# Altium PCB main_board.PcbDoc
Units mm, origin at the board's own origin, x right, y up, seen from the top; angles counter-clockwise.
Board outline 36 x 36 mm, 2 copper layers (Top Layer, Bottom Layer); 78 components, 59 nets, 251 pads, 295 vias.
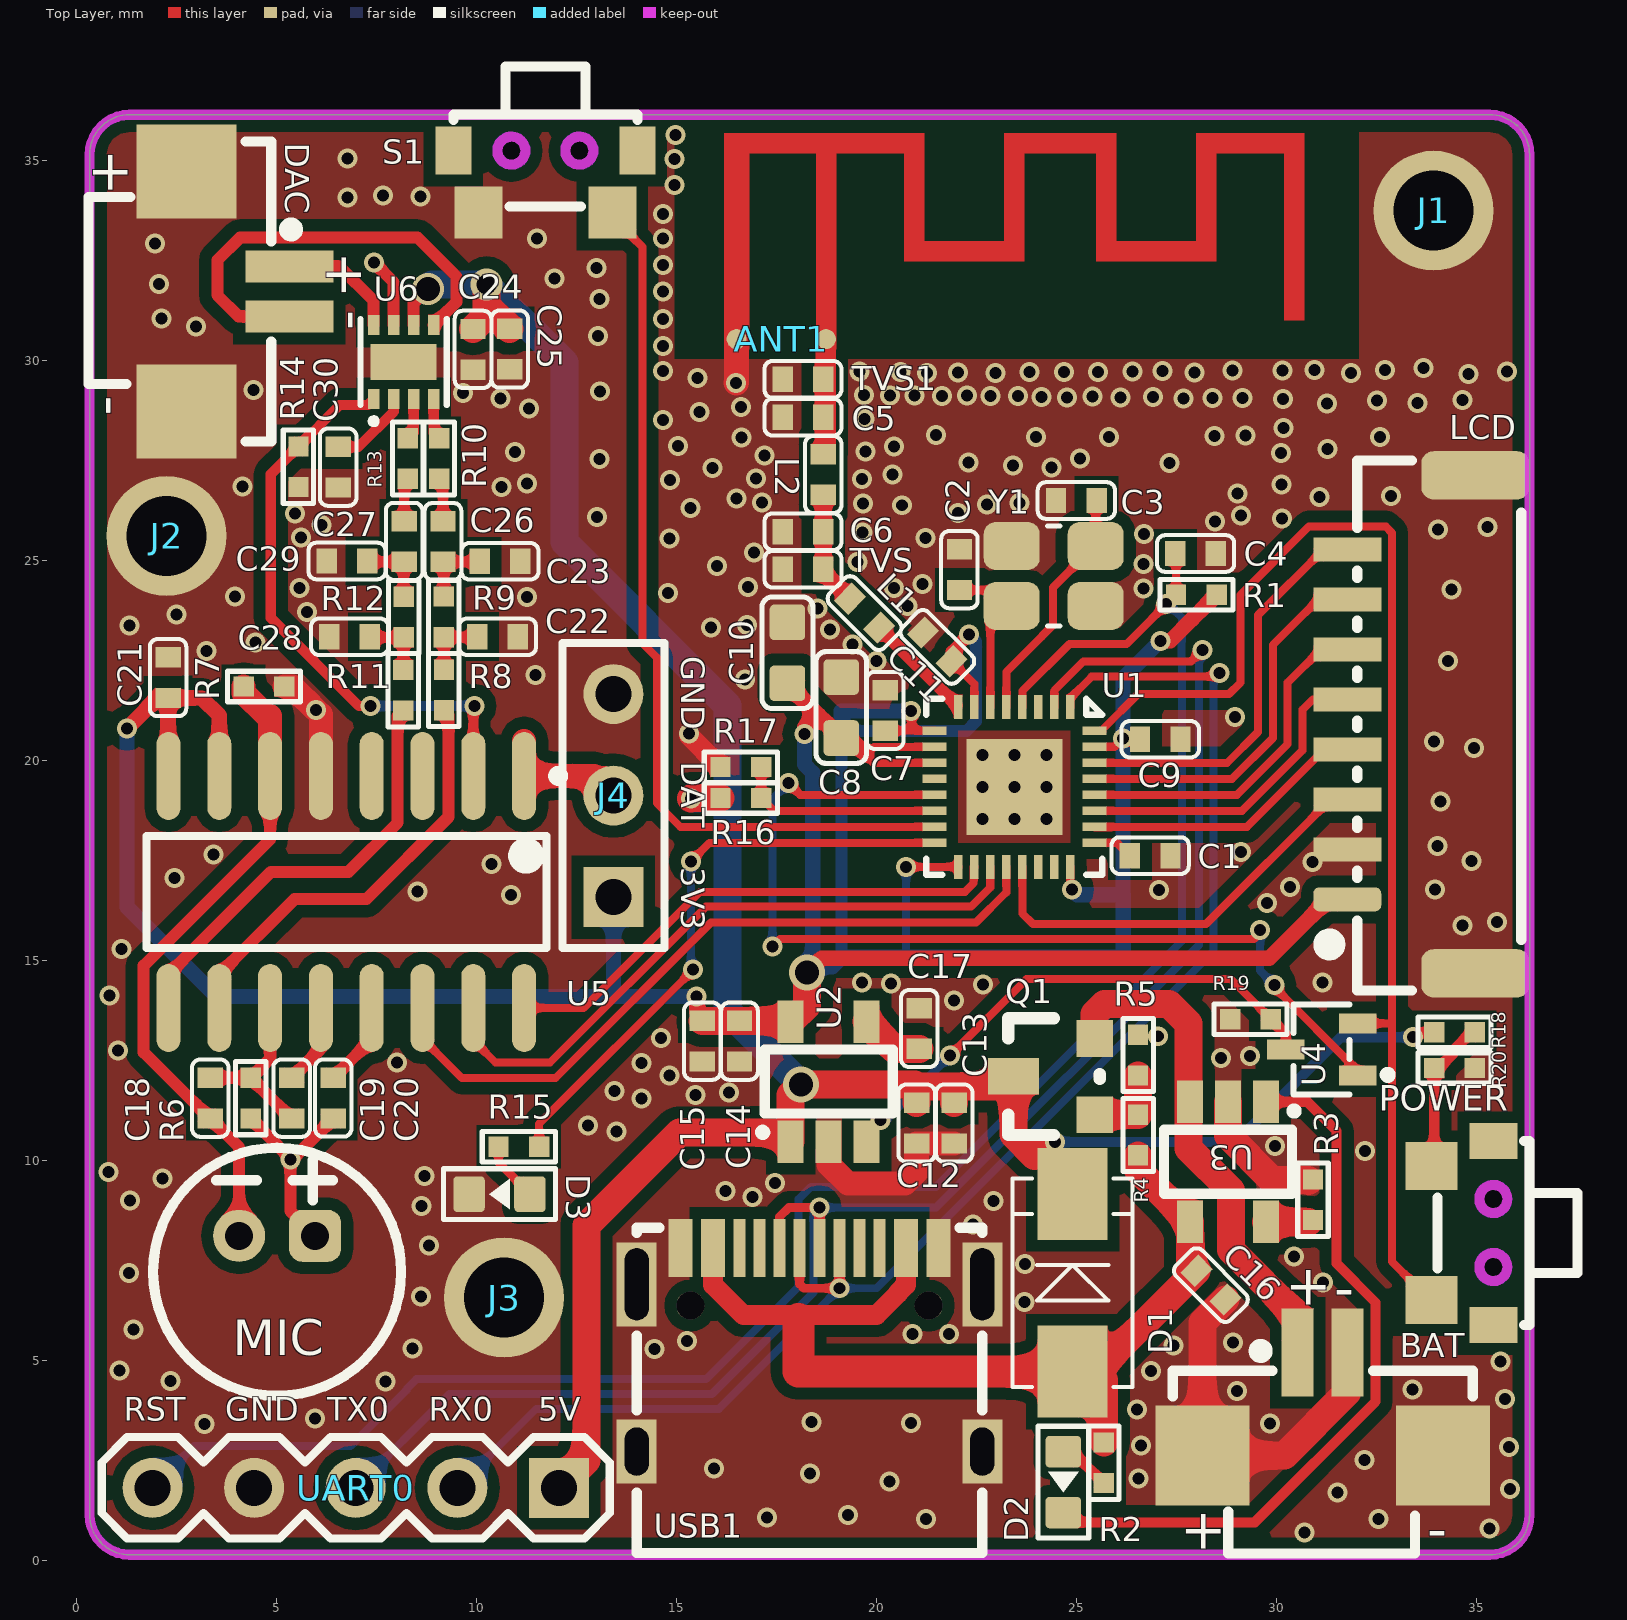
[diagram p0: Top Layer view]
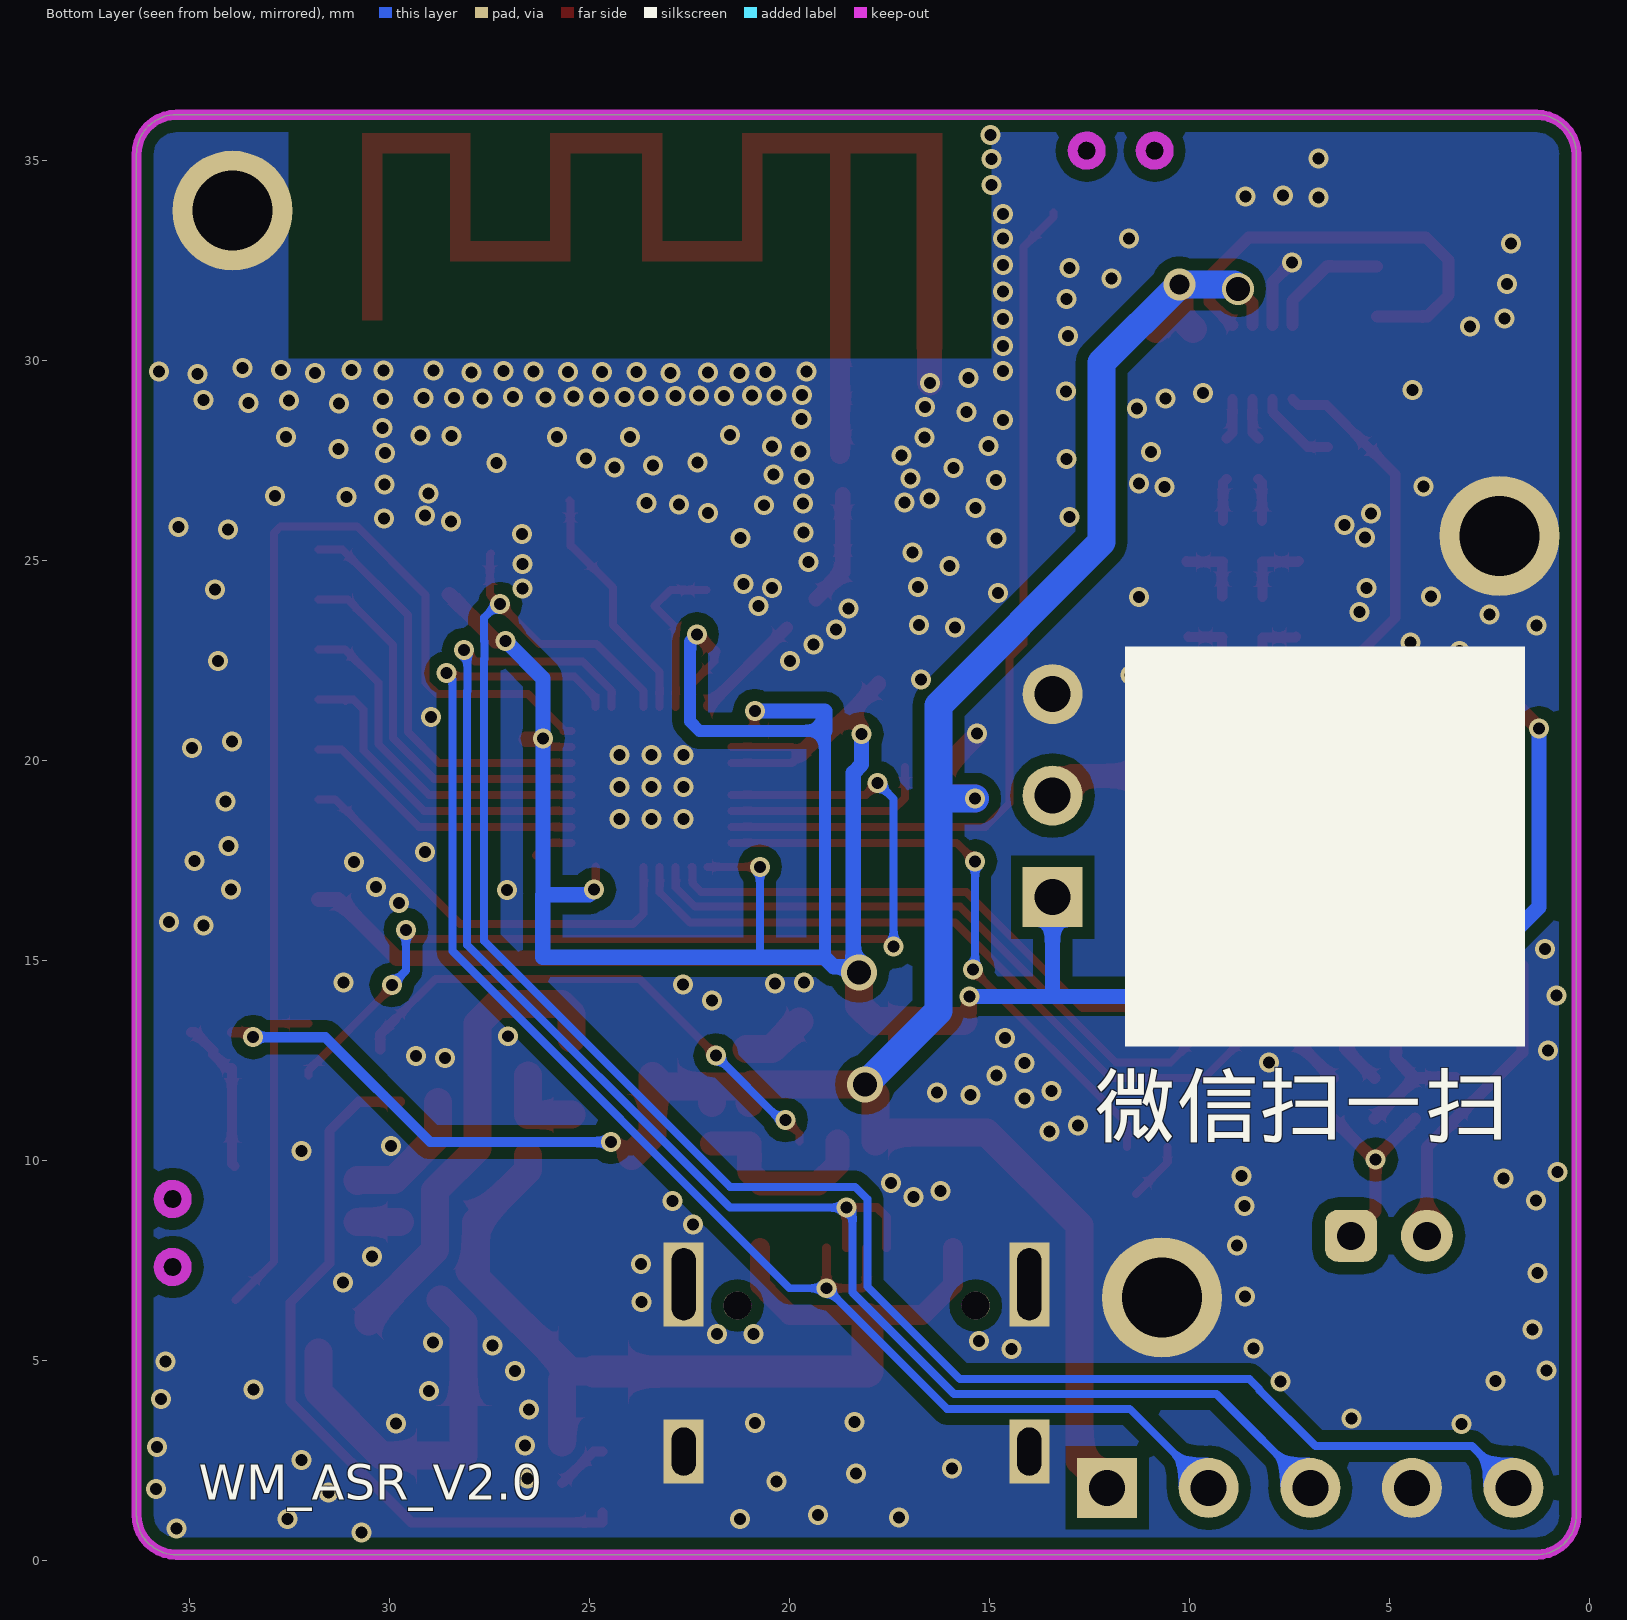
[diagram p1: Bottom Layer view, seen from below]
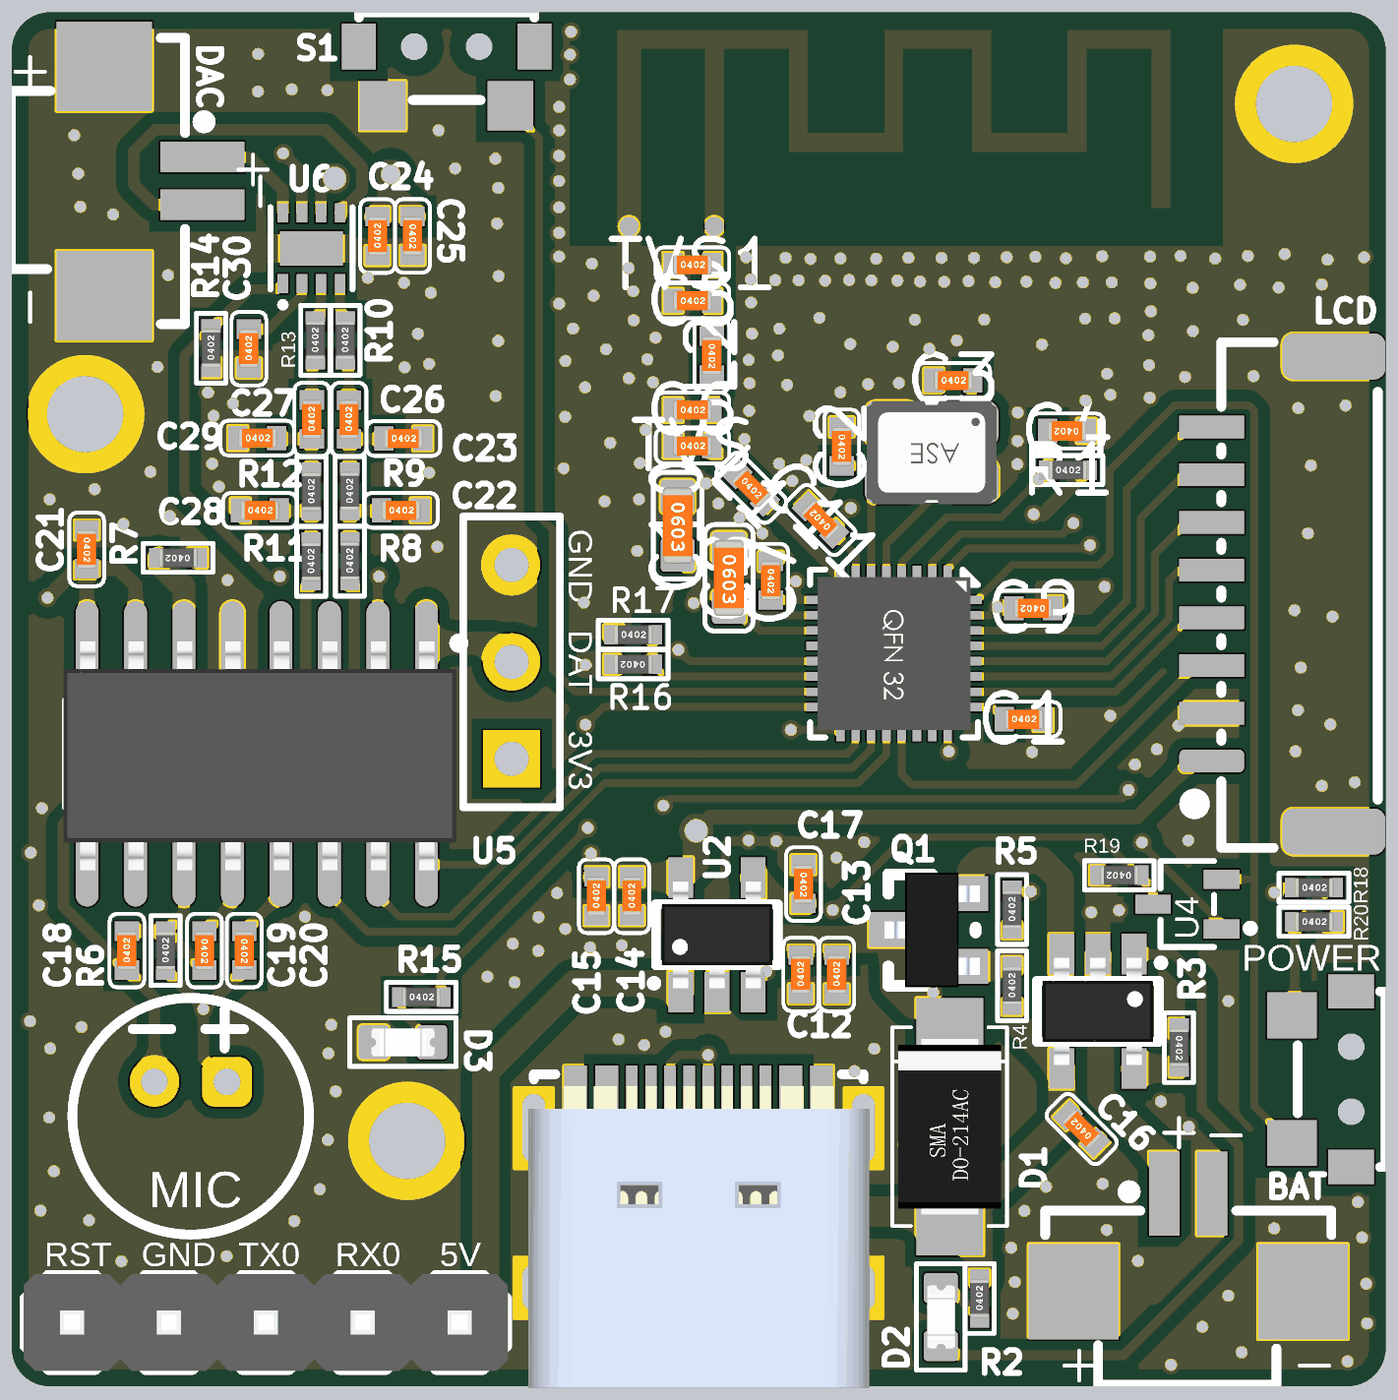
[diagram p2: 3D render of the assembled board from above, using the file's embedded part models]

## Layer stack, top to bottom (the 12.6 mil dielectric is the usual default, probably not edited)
Top Solder: solder mask 0.0102, Solder Resist, Dk 3.5
Top Layer: signal copper 0.0356
Dielectric 1: dielectric 0.32, FR-4, Dk 4.8
Bottom Layer: signal copper 0.0356
Bottom Solder: solder mask 0.0102, Solder Resist, Dk 3.5

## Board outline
0.338,1.149 ccw(c1.338,1.149) 1.338,0.149 35.338,0.149 ccw(c35.338,1.149) 36.338,1.149 36.338,35.149 ccw(c35.338,35.149) 35.338,36.149 1.338,36.149 ccw(c1.338,35.149) 0.338,35.149

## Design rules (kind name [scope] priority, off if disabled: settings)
Clearance Clearance_freep_ad [HasPad('Free-6') Or HasPad('Free-7') Or HasPad('Free-8') or HasPad('Free-HOLE')] p1: gap=1
Clearance polygon [inpolygon] p2: gap=0.3
Clearance ic [HasFootprint('LQFP48_N') Or HasFootprint('HMC5883L')or HasFootprint('RP4')or HasFootprint('USBMICRO2') Or HasFootprint('JP2_SMD')] p3: gap=0.102
Clearance [All And Not IsKeepOut vs All And Not IsKeepOut] p4: gap=0.17
ComponentClearance [InComponent('J1') vs InComponent('SW1')] p1 off: gap=0 collisioncheckmode=3 verticalgap=2540 showdistances=FALSE
DiffPairsRouting [All] p1: maxlimit=0.254 minlimit=0.2 mostfreqgap=0.2 toplayer_minwidth=0.381 toplayer_maxwidth=0.381 toplayer_prefwidth=0.381 bottomlayer_minwidth=0.381 bottomlayer_maxwidth=0.381 bottomlayer_prefwidth=0.381 maxuncoupledlength=12.7
FabricationTestpoint [(IsPad And (OnTopLayer Or OnBottomLayer))] p1: side=3 testpointundercomponent=TRUE minsize=1.016 maxsize=2.54 preferedsize=1.524 minholesize=0 maxholesize=1.016 preferedholesize=0.813 testpointgrid=0.025 allowsidetop=TRUE allowsidebottom=TRUE usegrid=TRUE gridtolerance=0
HoleSize [All] p1: absolutevalues=TRUE maxlimit=5.08 minlimit=0.152 maxpercent=80.000 minpercent=20.000
MinimumSolderMaskSliver [All] p1: minsoldermaskwidth=0.025
PolygonConnect PolygonConnect_1 [isvia] p1: connectstyle=Direct reliefconductorwidth=0.254 reliefentries=4 polygonreliefangle="90 Angle" airgapwidth=0.254
PolygonConnect [All] p2: connectstyle=Direct reliefconductorwidth=0.254 reliefentries=4 polygonreliefangle="90 Angle" airgapwidth=0.254
RoutingVias [All] p1: holewidth=0.35 width=0.7 viastyle="Through Hole" minholewidth=0.3 minwidth=0.35 maxholewidth=10 maxwidth=10
ShortCircuit [InNet('ANT1') vs InNet('GND')] p1: allowed=TRUE
SilkToSilkClearance [All] p1: silktosilkclearance=0
SilkToSolderMaskClearance SilkscreenOverComponentPads [IsPad] p1 off: minsilkscreentomaskgap=0.051 clearancetoexposedcopper=TRUE
SolderMaskExpansion [All] p1: expansion=0.051
Width Width_1 [InNet('VCC')] p1: maxlimit=25.4 minlimit=0.178 preferedwidth=0.635
Width [All] p2: maxlimit=10 minlimit=0.2 preferedwidth=0.254
22 further rules are at their usual default settings.

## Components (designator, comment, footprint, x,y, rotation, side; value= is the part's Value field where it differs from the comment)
ANT1 "PCB_ANT" MINI_ANT 18.747,30.517 r270 top
BAT "Header 2" CONN-SMD_2P-P1.25-HC-1.25-2PWT 31.165,3.914 r0 top locked
C1 "4.7uF/6.3V" C0402#1 26.853,17.628 r0 top
C2 "15pF" C0402#1 22.084,24.775 r270 top
C3 "15pF" C0402#1 25.006,26.505 r0 top
C4 "1uF/6.3V" C0402#1 27.987,25.18 r180 top
C5 "1pF" C0402#1 18.172,28.589 r0 top
C6 "1pF" C0402#1 18.172,25.725 r0 top
C7 "1nF/16V" C0402#1 20.226,21.257 r270 top
C8 "C0603/47uF/6.3V" C0603 19.129,21.329 r270 top locked
C9 "1uF/6.3V" C0402#1 27.104,20.536 r180 top
C10 "C0603/10uF/6.3V" C0603 17.784,22.697 r270 top
C11 "1uF/6.3V" C0402#1 21.53,22.845 r135 top
C12 "10uF" C0402#1 21.013,10.94 r90 top
C13 "100nF" C0402#1 21.953,10.94 r90 top
C14 "100nF" C0402#1 16.585,12.988 r90 top
C15 "10uF" C0402#1 15.655,12.988 r90 top
C16 "10uF" C0402#1 28.372,6.888 r135 top
C17 "22nF" C0402#1 21.08,13.305 r270 top
C18 "4.7uF/6.3V" C0402#1 3.355,11.563 r90 top
C19 "1uF/6.3V" C0402#2 3.349,11.563 r270 top
C20 "1uF/6.3V" C0402#1 6.428,11.564 r270 top
C21 "4.7uF/6.3V" C0402#1 2.299,22.077 r270 top
C22 "100pF" C0402#1 10.536,23.1 r0 top
C23 "100pF" C0402#1 10.597,24.984 r0 top
C24 "1uF/6.3V" C0402#1 9.922,30.285 r90 top
C25 "10uF/6.3V" C0402#1 10.839,30.29 r270 top
C26 "220nF" C0402#1 9.172,25.481 r90 top
C27 "220nF" C0402#1 8.201,25.482 r90 top
C28 "100pF" C0402#3 4.165,22.593 r0 top
C29 "100pF" C0402#1 6.772,24.993 r0 top
C30 "1uF/6.3V" C0402#4 5.756,27.494 r90 top
D1 "SS14" DO-214 24.915,6.948 r90 top locked
D2 "D0603_Red" D0603 24.682,1.964 r270 top locked
D3 "D0603_Blue" D0603 10.585,9.164 r180 top
DAC "Header 2" CONN-SMD_2P-P1.25-HC-1.25-2PWT 4.044,31.73 r270 top locked
J1 "M3" "M3 125X200" 33.938,33.749 r0 top
J2 "M3" "M3 125X200" 2.261,25.619 r0 top
J3 "M3" "M3 125X200" 10.7,6.578 r0 top
J4 "Header 3" HDR1X3 13.435,16.587 r90 top
L1 "8.2pF" 0402C 19.711,23.689 r315 top
L2 "2.4nH" 0402C 18.68,27.154 r270 top
LCD "Header_10" CONN-SMD_SM08B-GHS-TB-LF-SN 33.38,20.907 r90 top locked
MIC "GMI6027P-2C30DB" MIC-TH_BD6.0-P1.90-D0.4-L 5.026,7.223 r180 top
POWER "TS24CA" SW-SMD_TS24CA 35.432,10.492 r270 top (schematic designator Power)
Q1 "PMOS/AO3401" SOT-23 24.449,12.102 r90 top
R1 "4.7K" R0402 28.007,24.152 r0 top locked
R2 "1K" R0402 25.695,2.448 r90 top
R3 "1.65K" R0402 30.923,9.023 r270 top
R4 "10K" R0402 26.549,10.64 r90 top
R5 "100K" R0402 26.549,12.639 r90 top
R6 "2.2K" R0402 4.369,11.563 r90 top
R7 "0R" R0402 4.697,21.855 r180 top
R8 "40.2K" R0402 9.196,21.769 r90 top
R9 "40.2K" R0402 9.193,23.597 r90 top
R10 "22K" R0402 9.078,27.553 r90 top
R11 "40.2K" R0402 8.182,21.761 r90 top
R12 "40.2K" R0402 8.188,23.591 r90 top
R13 "22K" R0402 8.291,27.553 r90 top
R14 "100K" R0402 5.559,27.348 r90 top
R15 "1K" R0402 11.068,10.347 r0 top
R16 "10K/±1%" R0402 16.619,19.067 r180 top
R17 "10K/±1%" R0402 16.619,19.841 r0 top
R18 "5.1K" R0402 34.46,13.213 r0 top
R19 "1M" R0402 29.358,13.539 r180 top
R20 "10K" R0402 34.46,12.318 r0 top
S1 "TS24CA" SW-SMD_TS24CA 9.432,35.251 r0 top
TVS "BUE03CN10" C0402#1 18.172,24.787 r0 top
TVS1 "BUE03CN10" C0402#1 18.172,29.533 r0 top
U1 "W800" QFN32_4X4 23.455,19.348 r270 top locked
U2 "DS8572" SOT-23-5 18.815,11.978 r90 top locked
U3 "LTC4054" SOT-23-5 28.798,9.972 r270 top
U4 "BAT54CW" SOT-323-3_L2.0-W1.3-P1.30-LS2.3-BR 31.139,12.781 r0 top
U5 "WM8211" SOP-16 6.756,16.719 r270 top locked
U6 "HAA9209" DFN-8_L2.0-W2.0-P0.50-BL-EP 8.19,29.966 r0 top
UART0 "Header_5" PH_5PIN_DIP_2.54MM_180DEG 12.071,1.823 r180 top locked
USB1 "Type-C 母座 卧贴-直插" "Type-C 母座 卧贴-直插" 22.655,6.908 r0 top locked
Y1 "40MHz" OSC-TZ1067B 24.441,24.615 r180 top

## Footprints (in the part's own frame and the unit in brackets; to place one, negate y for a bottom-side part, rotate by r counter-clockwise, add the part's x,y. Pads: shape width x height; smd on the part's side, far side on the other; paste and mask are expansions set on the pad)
0402C [mil]
  rect 20x25 smd: 1(-20,0) 2(20,0)
  silkscreen extent -38,-18 38,18, body extent -20,-10 20,10, height 20
C0402#1 [mil]
  rect 20x25 smd: 1(-20,0) 2(20,0)
  silkscreen extent -38,-18 38,18, body extent -20,-10 20,10, height 20
C0402#2 [mil]
  rect 20x25 smd: 1(-20,80.28) 2(20,80.28)
  silkscreen extent -38,62 38,98, body extent -20,70 20,90, height 20
C0402#3 [mil]
  rect 20x25 smd: 1(85.2,19.92) 2(125.2,19.92)
  silkscreen extent 67,2 143,38, body extent 85,10 125,30, height 20
C0402#4 [mil]
  rect 20x25 smd: 1(-26.14,-31.3) 2(13.86,-31.3)
  silkscreen extent -44,-49 32,-13, body extent -26,-41 14,-21, height 20
C0603 [mil]
  rrect25% 35x35 smd: 1(-30,0) 2(30,0)
  silkscreen extent -55,-25 55,25, body extent -39,-15 39,16, height 31
CONN-SMD_2P-P1.25-HC-1.25-2PWT [mm]
  rect 0.8x2.2 smd paste+0 mask+0.05: 1(-0.625,1.285) 2(0.625,1.285)
  rect 2.35x2.5 smd paste+0 mask+0.05: 3(-3.005,-1.285) 4(3.005,-1.285)
  silkscreen extent -3.75,-3.73 3.75,1.48
CONN-SMD_SM08B-GHS-TB-LF-SN [mm]
  rrect50% 0.6x1.7 smd paste+0 mask+0.05: 1(-4.375,1.6)
  rect 0.6x1.7 smd paste+0 mask+0.05: 2(-3.125,1.6) 3(-1.875,1.6) 4(-0.625,1.6) 5(0.625,1.6) 6(1.875,1.6) 7(3.125,1.6) 8(4.375,1.6)
  rrect50% 1.21x2.7 smd paste+0 mask+0.05: 9(-6.225,-1.6) 10(6.225,-1.6)
  silkscreen extent -6.65,-2.75 6.6,2.25
D0603 [mil]
  rrect25% 31x35 smd: 1(-30,0) 2(30,0)
  silkscreen extent -55,-25 55,25, body extent -32,-14 32,15, height 27
DFN-8_L2.0-W2.0-P0.50-BL-EP [mm]
  rect 0.28x0.505 smd: 1(-0.75,-0.928) 2(-0.25,-0.928) 3(0.25,-0.928) 4(0.75,-0.928) 5(0.75,0.928) 6(0.25,0.928) 7(-0.25,0.928) 8(-0.75,0.928)
  rect 1.65x0.9 smd: 9(0,0)
  silkscreen extent -1.08,-1.55 1.08,1.08
DO-214 [mm]
  rect 2.3x1.75 smd: 1(-2.222,0) 2(2.223,0)
  silkscreen extent -2.6,-1.5 2.6,1.5, body extent -2.3,-1.35 2.3,1.35, height 2.4
HDR1X3 [mm] "Connector; Header; 3 Position"
  rect 1.5x1.5 hole 0.9: 1(0,0)
  round 1.5 hole 0.9: 2(2.54,0) 3(5.08,0)
  silkscreen extent -1.27,-1.27 6.35,1.27
"M3 125X200" [mm] "M3螺丝孔，孔125Mil，焊盘200Mil"
  round 3 hole 2: 1(0,0)
MIC-TH_BD6.0-P1.90-D0.4-L [mm]
  rrect50% 1.3x1.3 hole 0.7: 1(-0.95,-0.9)
  round 1.3 hole 0.7: 2(0.95,-0.9)
  silkscreen extent -3.1,-3.1 3.1,3.1
MINI_ANT [mm]
  rrect100% 0.5x0.5 smd: 1(-0.023,0) 2(-0.023,-2.236)
  Top Layer region: -4.673,-2.549 -5.173,-2.549 -5.173,2.451 -2.473,2.451 -2.473,4.451 -5.173,4.451 -5.173,7.251 -2.473,7.251 -2.473,9.251 -5.173,9.251 -5.173,11.951 -0.5,11.951 -0.5,11.451 -4.673,11.451 -4.673,9.751 -1.973,9.751 -1.973,6.751 -4.673,6.751 -4.673,4.951 -1.973,4.951 -1.973,1.951 -4.673,1.951 -4.673,0.251 0.227,0.251 0.227,-0.249 -4.673,-0.249 -4.673,-2.549
  Top Layer region: -4.926,-2.549 0.227,-2.549 0.227,-1.922 -4.926,-1.922 -4.926,-2.549
OSC-TZ1067B [mm]
  rrect50% 1.4x1.2 smd: 1(-1.05,-0.75) 2(1.05,-0.75) 3(1.05,0.75) 4(-1.05,0.75)
  silkscreen extent -0.15,-1.25 0.15,1.25, body extent -1.7,-1.35 1.7,1.35, height 1.06
PH_5PIN_DIP_2.54MM_180DEG [mm]
  rect 1.5x1.5 hole 0.9: 1(0,0)
  round 1.5 hole 0.9: 2(2.54,0) 3(5.08,0) 4(7.62,0) 5(10.16,0)
  silkscreen extent -1.27,-1.27 11.43,1.27, body extent -1.27,-1.27 11.43,1.27, height 8.02
QFN32_4X4 [mm]
  rect 0.6x0.22 smd: 1(-2,1.4) 2(-2,1) 3(-2,0.6) 4(-2,0.2) 5(-2,-0.2) 6(-2,-0.6) 7(-2,-1) 8(-2,-1.4) 17(2,-1.4) 18(2,-1) 19(2,-0.6) 20(2,-0.2) 21(2,0.2) 22(2,0.6) 23(2,1) 24(2,1.4)
  rect 0.22x0.6 smd: 9(-1.4,-2) 10(-1,-2) 11(-0.6,-2) 12(-0.2,-2) 13(0.2,-2) 14(0.6,-2) 15(1,-2) 16(1.4,-2) 25(1.4,2) 26(1,2) 27(0.6,2) 28(0.2,2) 29(-0.2,2) 30(-0.6,2) 31(-1,2) 32(-1.4,2)
  rect 2.4x2.4 smd: 33(0,0)
  silkscreen extent -2.2,-2.2 2.2,2.2, body extent -2,-2 2,2, height 0.57
R0402 [mil]
  rect 20x20 smd: 1(-20,0) 2(20,0)
  silkscreen extent -36,-15 36,15, body extent -20,-10 20,10, height 20
SOP-16 [mm]
  oval 2.2x0.6 smd: 1(-2.9,4.445) 2(-2.9,3.175) 3(-2.9,1.905) 4(-2.9,0.635) 5(-2.9,-0.635) 6(-2.9,-1.905) 7(-2.9,-3.175) 8(-2.9,-4.445) 9(2.9,-4.445) 10(2.9,-3.175) 11(2.9,-1.905) 12(2.9,-0.635) 13(2.9,0.635) 14(2.9,1.905) 15(2.9,3.175) 16(2.9,4.445)
  silkscreen extent -3.02,-5 1.4,5.42, body extent -2.95,-5.07 3.05,5.23, height 2.11
SOT-23 [mil]
  rect 36x36 smd: 1(-37.5,-40) 2(37.5,-40)
  rect 36x50 smd: 3(0.5,40)
  silkscreen extent -58,-45 58,45, body extent -59,-49 59,49, height 41
SOT-23-5 [mm]
  rect 1.06x0.65 smd: 1(-1.5,0.95) 2(-1.5,0) 3(-1.5,-0.95) 4(1.5,-0.95) 5(1.5,0.95)
  silkscreen extent -1.33,-1.6 0.8,1.71, body extent -1.4,-1.45 1.4,1.45, height 1.45
SOT-323-3_L2.0-W1.3-P1.30-LS2.3-BR [mm]
  rect 0.936x0.5 smd: 1(0.898,-0.65) 2(0.898,0.65) 3(-0.898,0)
  silkscreen extent -0.7,-1.13 1.75,1.13
SW-SMD_TS24CA [mm]
  rect 0.9x1.2 smd: 1(0,0) 2(4.6,0)
  rect 1.2x1.3 smd: 3(0.625,-1.55) 4(3.975,-1.55)
  Keep-Out Layer circle w0.005: c3.15,0 r0.35
  Keep-Out Layer circle w0.005: c1.45,0 r0.35
  Keep-Out Layer board cut-out: 1.45,0.35 1.38,0.35 1.252,0.297 1.153,0.198 1.1,0.07 1.1,-0.07 1.153,-0.198 1.252,-0.297 1.38,-0.35 1.45,-0.35 1.52,-0.35 1.648,-0.297 1.747,-0.198 1.8,-0.07 1.8,0.07 1.747,0.198 1.648,0.297 1.52,0.35 1.45,0.35 1.45,0.35
  Keep-Out Layer board cut-out: 3.15,0.35 3.08,0.35 2.952,0.297 2.853,0.198 2.8,0.07 2.8,-0.07 2.853,-0.198 2.952,-0.297 3.08,-0.35 3.15,-0.35 3.22,-0.35 3.348,-0.297 3.447,-0.198 3.5,-0.07 3.5,0.07 3.447,0.198 3.348,0.297 3.22,0.35 3.15,0.35 3.15,0.35
  Keep-Out Layer circle w0.254: c3.15,0 r0.35
  Keep-Out Layer circle w0.254: c1.45,0 r0.35
  silkscreen extent 0,-1.4 4.6,2.1
"Type-C 母座 卧贴-直插" [mm]
  rect 1x2.1 hole 0.6 slot 1.8 at 90 deg: 13(-8.64,0) 14(0,0)
  rect 1x1.6 hole 0.6 slot 1.2 at 90 deg: 15(-8.64,-4.18) 16(0,-4.18)
  rect 0.6x1.45 smd: A1B12(-7.545,0.915) A4B9(-6.73,0.915) B1A12(-1.1,0.915) B4A9(-1.91,0.915)
  rect 0.3x1.45 smd: A5(-5.57,0.914) A6(-4.57,0.915) A7(-4.07,0.915) A8(-3.07,0.915) B5(-2.57,0.915) B6(-3.57,0.915) B7(-5.07,0.915) B8(-6.07,0.915)
  round 0.7 hole 0.7 unplated: ""(-7.3,-0.53) ""(-1.34,-0.53)
  silkscreen extent -8.64,-6.71 0,1.42, body extent -8.79,-6.79 0.15,1.11, height 3.2

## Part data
ANT1: library part GPRS_PCB_ANT
BAT DAC: "Header, 2-Pin"
C1 C18 C21: library part C0402/4.7uF/6.3V
C2 C3 C5 C6 TVS TVS1: library part C0402/1.2pF/50V
C4 C9 C11 C19 C20 C24 C30: library part C0402/1uF/6.3V
C7 C17 C22 C23 C26 C27 C28 C29: library part C0402/1nF/16V
C12 C15 C16 C25: library part C0402/10uF/6.3V
C13 C14: library part C0402/100nF/16V
D1: library part M7
J1 J2 J3: "铜柱孔"
J4: "Header, 3-Pin"
L1: library part 2.2nH/L0402
L2: library part 15nH/L0402
LCD: library part 180DIP_PH_10
Q1: library part AO3401/SOT-23
R1: library part R0402/4.7K
R2 R15: library part R0402/1K
R3 R7: library part R0402/0R
R4: library part R0402/10K
R5 R8 R9 R10 R11 R12 R13 R14 R18 R19 R20: library part R0402/100K
R6: library part R0402/2K
R16 R17: library part R0402/10K±1%
U1: library part W800/QFN32
U4: library part BAT54CW_C22392482
UART0: library part 180DIP_PH_5
Y1: library part 82J0626-25MHz, "X-tal 25MHz,3.2x2.5 SMD, CL=18pF"

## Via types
v1: diameter 0.5, hole 0.3, Top Layer to Bottom Layer, tented both sides, 291 vias
v2: diameter 0.9, hole 0.6, Top Layer to Bottom Layer, tented both sides, 2 vias
v3: diameter 0.8, hole 0.5, Top Layer to Bottom Layer, tented both sides, 1 vias
v4: diameter 0.8, hole 0.6, Top Layer to Bottom Layer, tented both sides, 1 vias

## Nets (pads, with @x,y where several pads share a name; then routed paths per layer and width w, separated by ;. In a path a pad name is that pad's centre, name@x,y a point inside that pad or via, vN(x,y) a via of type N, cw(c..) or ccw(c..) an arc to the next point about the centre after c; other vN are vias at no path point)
3V3: C7.2 C8.2 C9.2 C10.2 C11.1 C14.2 C15.2 C21.2 J4.1 LCD.1 R1.2 U1.7 U1.9 U1.10 U1.11 U1.17 U1.24 U1.31 U2.5 U5.7 U5.8 | length 102.3
  Top Layer w0.2: C7.2 20.891,20.749 ; v1(20.753,17.348) U1.17 ; v1(20.879,21.239) 20.891,21.227 20.891,20.749 ; U1.11 19.942,19.948 19.742,20.148 19.942,20.348 U1.10 ; U1.9 21.454,20.749 20.891,20.749 ; C11.1@21.889,22.725 C11.1 22.455,21.92 U1.7 ; U1.31 25.965,20.348 v1(26.176,20.559)
  Top Layer w0.22: v1@24.855,16.817 U1.24
  Top Layer w0.3: C11.1@21.889,22.725 v1(22.324,23.16)
  Top Layer w0.381: v1(1.272,20.809) 2.032,21.569 C21.2 ; U5.8 2.299,19.631 C21.2 ; U5.7 3.581,21.128 3.14,21.569 C21.2 ; v1(15.516,14.105) 15.516,13.72 15.634,13.603 15.591,13.56 C15.2 ; C10.2 17.784,21.912 18.534,21.162 ; v1(18.208,20.667) 18.208,20.836 18.534,21.162 ; v2(18.271,14.702) 18.632,15.063 29.832,15.063 31.3,16.532 LCD.1 ; 19.742,20.148 19.323,20.567 C8.2 18.534,21.162 ; v1(26.176,20.559) 26.198,20.536 C9.2 ; v1(27.114,22.998) 27.361,22.998 27.9,23.537 27.902,23.537 28.114,23.749 28.114,23.751 R1.2
  Top Layer w0.5: U2.5@17.847,13.496 U2.5
  Top Layer w0.7: C15.2 C14.2 U2.5@17.847,13.496 ; U2.5 18.271,13.884 v2(18.271,14.702)
  Bottom Layer w0.2: v1(20.753,17.348) 20.753,15.198 20.864,15.087
  Bottom Layer w0.3: 19.129,15.087 19.129,20.748 22.264,20.748 22.498,20.982 22.498,22.986 v1(22.324,23.16)
  Bottom Layer w0.381: v1(1.272,20.809) 1.272,16.338 3.505,14.105 13.51,14.105 ; J4.1 13.435,14.18 13.51,14.105 ; v1(15.516,14.105) 13.51,14.105 ; v1(18.208,20.667) 18.208,19.904 18.416,19.697 v2@18.416,14.847 ; v2(18.271,14.702) v2@18.416,14.847 ; 19.129,20.748 19.129,21.239 v1(20.879,21.239) ; v1(24.892,16.78) 25.025,16.647 26.177,16.647 26.177,15.087 20.864,15.087 19.144,15.087 18.904,14.847 v2@18.416,14.847 ; 26.176,16.702 v1(26.176,20.559) 26.176,22.06 v1(27.114,22.998)
A0: U1.13 U4.1 | length 25.1
  Top Layer w0.2: v1@17.406,15.364 v1(17.41,15.36) 17.595,15.545 29.45,15.545 29.599,15.694 v1(29.599,15.77) ; v1(17.805,19.444) 18.101,19.148 U1.13 ; v1(29.954,14.397) 29.954,14.341 32.037,12.258 U4.1
  Bottom Layer w0.2: v1(17.41,15.36) 17.41,19.041 17.406,19.045 v1(17.805,19.444) ; v1(29.599,15.77) 29.599,14.752 v1(29.954,14.397)
A1: R16.1 R17.2 U1.14 | length 5.2
  Top Layer w0.2: R17.2 R16.1 17.446,18.748 U1.14
A4: S1.4 U1.15 | length 22.4
  Top Layer w0.2: S1.4 13.407,33.592 14.158,32.841 14.158,22.936 14.517,22.577 14.517,18.937 15.106,18.348 U1.15
A7: R15.2 U1.16 | length 15
  Top Layer w0.2: R15.2 11.576,10.922 v1(15.429,14.775) ; v1(15.369,17.483) 15.834,17.948 U1.16
  Bottom Layer w0.2: v1(15.369,17.483) 15.369,14.835 v1(15.429,14.775)
AGND: C18.1 MIC.2 R7.2 U5.6 | length 16.4
  Top Layer w0.3: MIC.2 4.076,10.334 C18.1 2.913,11.497 2.904,11.497 1.691,12.711 1.691,14.876 4.851,18.036 U5.6
  Top Layer w0.6: R7.2 4.189,21.698 4.769,21.118 4.851,21.118 U5.6
ANT: L1.2 U1.8 | length 2.8
  Top Layer w0.3: L1.2 20.073,23.33 U1.8@22.025,21.378
ANT1: ANT1.1 C5.2 L2.1 TVS1.2 | length 2.7
  Top Layer w0.5: L2.1@18.747,27.662 18.747,29.533 ANT1.1@18.747,30.39
B0: U1.18 U5.16 | length 13
  Top Layer w0.2: U5.16 12.691,13.819 15.592,16.72 22.219,16.72 22.435,16.936 22.435,17.348 U1.18
B1: U1.19 U5.15 | length 16.3
  Top Layer w0.2: U5.15 9.931,13.009 10.491,12.449 11.844,12.449 15.745,16.35 22.372,16.35 22.855,16.833 U1.19
B2: U1.20 U5.14 | length 18.3
  Top Layer w0.2: U5.14 8.661,13.049 9.649,12.061 11.979,12.061 15.87,15.952 22.497,15.952 23.255,16.71 U1.20
B3: LCD.3 U1.21 | length 10.7
  Top Layer w0.2: U1.21 23.655,16.18 23.92,15.915 28.251,15.915 31.368,19.032 LCD.3
B4: U1.22
B5: U1.23
B6: LCD.4 U1.26 | length 7.5
  Top Layer w0.2: 25.87,18.336 25.467,18.336 U1.26 29.271,18.348 31.205,20.282 LCD.4
B7: LCD.5 U1.27 | length 8.1
  Top Layer w0.2: U1.27 29.148,18.748 30.66,20.26 30.66,21.275 30.917,21.532 LCD.5@31.154,21.532 ; LCD.5@31.112,21.49 LCD.5@31.154,21.532 ; LCD.5 LCD.5@31.154,21.532
B8: LCD.6 U1.28 | length 8.7
  Top Layer w0.2: U1.28 29.024,19.148 30.29,20.414 30.29,21.951 31.121,22.782 LCD.6
B9: LCD.7 U1.29 | length 9.5
  Top Layer w0.2: U1.29 28.901,19.548 29.92,20.567 29.92,22.898 31.054,24.032 LCD.7
B10: LCD.8 U1.30 | length 10.2
  Top Layer w0.2: U1.30 28.778,19.948 29.55,20.72 29.55,23.64 31.192,25.282 LCD.8
B11: POWER.4 U1.32 U4.2 | length 31.4
  Top Layer w0.2: U1.32 25.656,20.748 25.656,20.774 26.548,21.666 28.826,21.666 29.109,21.949 29.109,24.143 30.818,25.852 32.742,25.852 32.9,25.694 32.9,13.378 ; U4.2 32.847,13.431 32.9,13.378 ; POWER.4@33.858,6.517 32.9,7.475 32.9,13.378
D+: U1.1 UART0.2 USB1.A6 USB1.B6 | length 38.6
  Top Layer w0.2: U1.1 24.855,21.566 25.389,22.1 28.503,22.1 v1(28.589,22.186)
  Top Layer w0.22: USB1.A6 18.085,6.921 18.195,6.811 v1(19.085,6.811) USB1.B6
  Bottom Layer w0.2: UART0.2 11.506,3.798 16.072,3.798 v1(19.085,6.811) 20.008,6.811 28.439,15.243 28.439,21.899 28.437,21.901 28.437,22.034 v1(28.589,22.186)
D-: U1.2 UART0.3 USB1.A7 USB1.B7 | length 43.2
  Top Layer w0.2: U1.2 24.455,21.752 25.181,22.478 27.869,22.478 v1(28.154,22.763)
  Top Layer w0.22: USB1.B7 17.585,8.594 17.819,8.828 v1(18.585,8.828) USB1.A7
  Bottom Layer w0.2: UART0.3@6.991,2.368 UART0.3 9.336,4.168 15.898,4.168 18.435,6.705 18.435,8.678 v1(18.585,8.828) 21.501,8.828 28.069,15.396 28.069,21.745 28.067,21.748 28.067,22.676 v1(28.154,22.763)
DSM_N: R8.1 U5.10 | length 10.9
  Top Layer w0.3: U5.10 3.581,14.657 5.461,16.537 7.256,16.537 9.311,18.592 9.311,21.146 R8.1
DSM_P: R11.1 U5.9 | length 11
  Top Layer w0.3: U5.9 2.311,14.658 4.872,17.219 6.811,17.219 8.041,18.449 8.041,21.112 R11.1
GND: ANT1.2 BAT.2 BAT.3 BAT.4 C1.2 C2.1 C3.1 C4.1 C5.1 C6.1 C7.1 C8.1 C9.1 C10.1 C11.2 C12.1 C13.1 C14.1 C15.1 C16.1 C17.1 C21.1 C22.2 C23.2 C24.1 C25.2 C28.1 C29.1 C30.1 D3.2 DAC.3 DAC.4 J1.1 J2.1 J3.1 J4.3 LCD.2 LCD.9 LCD.10 R3.1 R5.2 R7.1 R14.1 R17.1 R19.2 R20.2 S1.3 TVS1.1 TVS.1 U1.33 U2.2 U3.2 U5.5 U6.7 U6.9 UART0.4 USB1.13 USB1.14 USB1.15 USB1.16 USB1.A1B12 USB1.B1A12 Y1.2 Y1.4 | length 24.1
  Top Layer w0.3: v1(7.448,32.453) 7.94,31.961 U6.7
  Top Layer w0.5: v1(15.326,20.681) 15.326,20.626 R17.1
  Top Layer w0.6: R7.1 5.407,21.855 v1(5.992,21.27) ; U5.5 v1@6.121,21.155 ; U2.2 18.815,9.908 19.295,9.428 20.72,9.428 21.013,9.721 C12.1 C13.1
  Top Layer w0.63: v1(16.502,29.446) 16.511,29.455 ANT1.2
  Top Layer w0.7: C16.1 28.16,5.958 BAT.3 30.205,2.629 31.79,4.214 BAT.2 ; U3.2 28.798,10.627 29.903,9.522 30.806,9.522 R3.1@30.806,9.489
  other v1: 30.712,0.71 35.339,0.8 21.251,1.042 32.563,1.038 17.278,1.08 19.299,1.147 31.533,1.705 35.85,1.796 20.33,1.983 26.565,2.05 18.353,2.175 15.953,2.309 32.214,2.52 35.828,2.836 26.623,2.881 3.208,3.421 29.847,3.431 18.391,3.461 20.868,3.442 5.967,3.554 26.527,3.777 35.72,4.045 29.028,4.244 33.415,4.282 7.739,4.474 2.362,4.496 1.089,4.749 26.868,4.743 35.609,4.974 8.408,5.31 14.462,5.298 27.438,5.376 28.923,5.453 15.276,5.493 20.91,5.672 21.822,5.664 1.441,5.78 23.708,6.47 8.618,6.603 31.178,6.95 1.317,7.188 23.723,7.416 30.448,7.609 8.826,7.874 22.418,8.405 8.633,8.87 1.344,8.999 22.936,8.992 16.908,9.091 16.239,9.236 17.469,9.436 2.162,9.561 8.708,9.62 0.815,9.714 32.217,10.241 29.978,10.363 13.512,10.731 12.8,10.878 14.134,11.555 15.49,11.648 16.321,11.701 13.464,11.744 14.841,12.134 8.019,12.453 14.138,12.441 28.621,12.566 29.35,12.619 1.048,12.75 14.622,13.071 27.043,13.111 21.946,13.999 0.833,14.13 22.674,14.404 20.371,14.431 19.643,14.453 31.165,14.452 1.129,15.295 34.666,15.879 35.526,15.973 29.769,16.44 10.877,16.642 8.534,16.73 27.072,16.766 33.976,16.786 30.343,16.84 2.459,17.069 10.38,17.412 30.904,17.462 34.888,17.49 3.431,17.656 29.123,17.719 34.037,17.862 22.655,18.548 23.455,18.548 24.255,18.548 34.112,18.98 22.655,19.348 23.455,19.348 24.255,19.348 22.655,20.148 23.455,20.148 24.255,20.148 34.944,20.313 33.95,20.479 28.976,21.093 16.725,22.035 11.49,22.145 20.004,22.495 34.3,22.497 3.264,22.741 19.409,22.906 4.48,22.949 18.85,23.279 15.872,23.333 1.331,23.384 16.773,23.391 2.508,23.653 5.767,23.72 18.535,23.807 20.789,23.869 11.272,24.087 3.971,24.107 14.797,24.198 34.379,24.274 26.686,24.309 5.587,24.321 16.796,24.336 20.443,24.323 21.155,24.414 16.017,24.867 26.691,24.917 19.535,24.964 16.942,25.205 14.837,25.549 5.624,25.574 21.236,25.572 26.696,25.665 19.657,25.706 34.046,25.777 35.287,25.846 6.136,25.897 28.473,25.978 30.153,26.052 13.017,26.095 29.123,26.128 5.476,26.185 22.046,26.194 15.361,26.323 20.653,26.386 22.773,26.407 19.669,26.431 23.583,26.437 17.142,26.455 16.506,26.559 31.081,26.595 32.874,26.615 29.037,26.677 4.156,26.857 10.633,26.847 30.138,26.906 11.273,26.935 14.844,27.013 16.992,27.055 19.647,27.041 20.415,27.16 15.912,27.319 24.38,27.331 23.42,27.385 27.331,27.443 22.308,27.454 13.081,27.537 25.101,27.55 17.206,27.624 30.12,27.69 10.978,27.723 19.732,27.73 31.287,27.797 15.042,27.862 20.449,27.86 16.633,28.079 24.002,28.092 25.818,28.095 32.598,28.092 28.462,28.12 29.236,28.128 21.5,28.143 30.187,28.314 14.678,28.513 19.709,28.544 15.581,28.723 11.319,28.801 16.621,28.841 31.278,28.93 33.534,28.939 32.519,29.008 34.666,29.018 10.616,29.06 27.686,29.058 30.172,29.045 24.77,29.086 26.106,29.077 26.922,29.091 28.404,29.072 29.159,29.072 21.65,29.118 23.542,29.119 24.137,29.095 25.408,29.105 20.342,29.131 20.954,29.126 22.277,29.134 22.862,29.123 19.702,29.147 9.667,29.191 13.094,29.236 4.434,29.263 15.539,29.563 34.814,29.668 21.267,29.688 22.051,29.699 22.986,29.692 27.958,29.701 31.869,29.698 19.581,29.729 20.613,29.718 23.831,29.718 24.699,29.714 25.551,29.714 35.77,29.728 14.678,29.747 26.407,29.733 27.16,29.743 30.165,29.751 28.907,29.757 30.962,29.767 32.726,29.767 33.691,29.816 14.678,30.368 13.051,30.615 2.994,30.853 14.678,31.036 2.132,31.054 13.085,31.548 14.678,31.729 2.078,31.923 11.956,32.058 13.009,32.313 14.678,32.39 1.971,32.926 11.523,33.055 14.678,33.056 14.678,33.67 6.785,34.074 8.607,34.108 7.673,34.13 14.96,34.389 6.789,35.057 14.963,35.04 14.991,35.638
LOAD: J4.2 U5.1 | length 3.3
  Top Layer w0.6: U5.1@11.201,20.493 U5.1 12.943,19.619 J4.2
MIC_N: C19.1 U5.12 | length 2.1
  Top Layer w0.3: C19.1 6.121,12.805 U5.12
MIC_P: C20.1 U5.13 | length 2.1
  Top Layer w0.3: C20.1 7.391,13.036 U5.13
NetC1_1: C1.1 U1.25 | length 1
  Top Layer w0.2: U1.25 26.025,17.948 C1.1
NetC2_2: C2.2 U1.6 Y1.3 | length 4.2
  Top Layer w0.2: C2.2 22.989,24.267 Y1.3 22.855,23.329 U1.6
NetC3_2: C3.2 U1.5 Y1.1 | length 6.1
  Top Layer w0.2: U1.5 23.255,22.216 24.148,23.109 24.148,23.116 24.425,23.393 24.425,24.33 25.46,25.365 Y1.1 25.491,26.482 C3.2
NetC6_2: C6.2 L1.1 L2.2 TVS.2 | length 2.9
  Top Layer w0.381: L2.2 C6.2 TVS.2 18.68,24.72 L1.1
NetC17_2: C17.2 U2.4 | length 1.6
  Top Layer w0.7: U2.4 20.446,12.797 C17.2
NetC20_2: C20.2 MIC.1 R6.1 | length 5
  Top Layer w0.3: R6.1 4.75,10.674 4.75,10.669 v1@5.356,10.063 ; v1(5.356,10.029) 5.356,8.743 MIC.1 ; v1@5.4,10.029 C20.2
NetC22_1: C22.1 R8.2 R9.1 | length 1.7
  Top Layer w0.254: R8.2 9.196,23.086 R9.1 10.017,23.089 C22.1
NetC23_1: C23.1 C26.1 R9.2 | length 1.8
  Top Layer w0.254: R9.2 9.193,24.952 C26.1 10.078,24.973 C23.1
NetC26_2: C26.2 R10.1 | length 1.1
  Top Layer w0.254: R10.1 9.172,26.951 C26.2
NetC27_1: C27.1 C29.2 R12.2 | length 1.8
  Top Layer w0.254: C29.2 7.299,24.974 C27.1 8.188,24.961 R12.2
NetC27_2: C27.2 R13.1 | length 1.1
  Top Layer w0.254: C27.2 8.201,26.955 R13.1
NetC28_2: C28.2 R11.2 R12.1 | length 1.7
  Top Layer w0.254: C28.2 7.361,23.083 R12.1 8.182,23.077 R11.2
NetC30_2: C30.2 U6.2 | length 2.1
  Top Layer w0.254: C30.2 7.06,27.846 7.94,28.726 U6.2
NetD2_1: D2.1 R2.1 | length 1.3
  Top Layer w0.254: D2.1 24.909,2.726 R2.1
NetD2_2: D2.2 U3.1 | length 18.5
  Top Layer w0.254: D2.2 24.682,0.958 29.469,0.958 32.487,3.976 32.487,6.456 31.514,7.429 31.514,10.741 30.783,11.472 U3.1
NetD3_1: D3.1 R15.1 | length 1.5
  Top Layer w0.2: R15.1 10.56,9.951 D3.1
NetPower_3: POWER.3 R18.2 R20.1 | length 3.9
  Top Layer w0.254: POWER.3 33.952,9.937 R20.1 34.073,12.318 34.417,12.662 34.417,12.75 34.88,13.213 R18.2
NetQ1_1: Q1.1 R4.2 R5.1 | length 2.1
  Top Layer w0.7: Q1.1 R4.2 R4.2 R5.1
NetR3_2: R3.2 U3.5 | length 1.1
  Top Layer w0.7: U3.5 R3.2@30.805,8.472
NetR10_2: R10.2 U6.4 | length 1
  Top Layer w0.254: U6.4 8.94,28.199 R10.2
NetR13_2: R13.2 U6.3 | length 1
  Top Layer w0.254: R13.2 8.44,28.21 U6.3
PA_SD: R14.2 U5.2 U6.1 | length 14.7
  Top Layer w0.254: v1(7.361,21.367) 7.069,21.367 4.866,23.57 4.866,27.163 R14.2 6.593,28.89 7.291,28.89 U6.1 ; U5.2 9.931,21.341 v1(9.957,21.367)
  Bottom Layer w0.254: v1(7.361,21.367) v1(9.957,21.367)
POWER: R19.1 U2.3 U4.3 | length 13.2
  Top Layer w0.2: U2.3 19.765,10.672 v1(20.111,11.018) ; v1(21.85,12.627) 23.764,14.541 28.864,14.541 R19.1
  Top Layer w0.254: R19.1 30.241,13.164 U4.3
  Bottom Layer w0.2: v1(20.111,11.018) 20.241,11.018 v1(21.85,12.627)
RESET: C4.2 R1.1 U1.4 UART0.5 | length 47.9
  Top Layer w0.2: U1.4 23.655,21.74 24.832,22.917 26.264,22.917 R1.1 27.499,25.16 C4.2
  Bottom Layer w0.2: UART0.5@1.646,1.789 UART0.5@1.911,1.789 ; UART0.5 2.952,2.864 6.864,2.864 8.259,4.259 8.259,4.284 8.513,4.538 15.745,4.538 18.065,6.858 18.065,9.043 18.37,9.348 21.498,9.348 27.643,15.493 27.643,22.539 27.634,22.548 27.634,22.979 27.643,22.987 27.643,23.581 27.306,23.918 v1(27.244,23.918)
SPK+: DAC.1 U6.8 | length 3.1
  Top Layer w0.3: DAC.1 6.58,32.355 7.44,31.495 U6.8
SPK-: DAC.2 U6.5 | length 11
  Top Layer w0.3: DAC.2 4.066,31.105 3.533,31.638 3.533,32.512 4.096,33.075 8.537,33.075 9.516,32.096 9.516,31.47 U6.5
USB_VBUS: C16.2 D1.1 R2.2 R4.1 U3.4 USB1.A4B9 USB1.B4A9 | length 25
  Top Layer w0.5: USB1.A4B9 15.925,6.897 16.681,6.141 20.008,6.141 20.545,6.678 20.545,6.697 20.745,6.897 USB1.B4A9
  Top Layer w0.7: D1.1 D1.1@25.491,4.726 ; R2.2 25.695,4.522 D1.1@25.491,4.726 ; R4.1 26.549,9.771 U3.4 27.848,7.175 C16.2@27.894,7.129 ; C16.2 C16.2@27.894,7.129 ; D1.1@25.491,4.726 C16.2@27.894,7.129
  Top Layer w0.8: 18.06,6.038 18.06,4.726 D1.1
VBAT: BAT.1 Q1.2 U3.3 | length 11.9
  Top Layer w0.7: Q1.2 25.465,13.673 25.713,13.921 27.322,13.921 27.813,13.43 27.813,10.306 28.868,9.251 28.868,7.762 30.531,6.099 30.54,6.099 BAT.1@30.54,5.981
VIN: C12.2 C13.2 C24.2 C25.1 D1.2 Q1.3 R16.2 R18.1 U2.1 U6.6 UART0.1 | length 63.9
  Top Layer w0.254: 23.964,10.122 24.309,10.467 v1(24.478,10.467) ; v1(33.42,13.087) 33.546,13.213 R18.1
  Top Layer w0.3: U6.6 8.44,31.442 v4(8.796,31.798)
  Top Layer w0.7: C24.2 10.266,31.137 10.266,31.371 ; v3(10.266,31.9) 10.266,31.371 ; C25.1 10.266,31.371 ; UART0.1 12.755,2.507 12.755,8.382 15.081,10.708 17.635,10.708 U2.1 17.865,11.644 v2(18.122,11.901) 19.48,11.901 ; v1(15.369,19.049) 15.387,19.067 R16.2 ; 19.478,11.903 20.967,11.903 21.013,11.857 ; C12.2 21.013,11.857 ; C13.2 21.953,11.751 22.059,11.857 ; 23.964,10.122 23.433,10.652 Q1.3 23.175,11.857 22.059,11.857 ; 21.013,11.857 22.059,11.857
  Bottom Layer w0.254: v1(24.478,10.467) 28.993,10.467 31.613,13.087 v1(33.42,13.087)
  Bottom Layer w0.3: 16.286,17.855 16.319,17.822
  Bottom Layer w0.7: v4(8.796,31.798) 8.898,31.9 v3(10.266,31.9) 10.266,31.892 12.207,29.951 12.207,25.464 16.286,21.385 16.286,19.021 ; v1(15.369,19.049) 16.258,19.049 16.286,19.021 ; v2(18.122,11.901) 16.286,13.737 16.286,17.855 16.286,19.021
VMIC: C18.2 C19.2 R6.2 U5.11 | length 4.4
  Top Layer w0.3: C18.2 R6.2 4.75,12.453 4.75,12.458 4.851,12.559 U5.11 ; R6.2@4.369,12.066 5.379,11.055 C19.2
WAKEUP: U1.3
pads on no net: POWER.1 POWER.2 S1.1 S1.2 U1.12 U5.3 U5.4 USB1. USB1.A5 USB1.A8 USB1.B5 USB1.B8

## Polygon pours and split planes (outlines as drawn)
GND on Top Layer "Top Layer-No Net" (solid, remove dead copper, pour order 0): -3.145,43.683 39.757,43.683 39.757,21.341 39.757,-6.142 -3.064,-6.142
GND on Bottom Layer "GND_L02_P002" (solid, remove dead copper, pour order 2): -4.009,39.004 43.704,39.004 43.704,16.662 43.704,-2.12 -3.942,-2.12

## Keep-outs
Keep-Out Layer:
  the board outline again, w0.254

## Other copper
Top Layer:
  pour cut-out: 14.96,36.112 32.078,36.112 32.078,30.03 14.96,30.03
Bottom Layer:
  pour cut-out: 14.96,36.096 32.538,36.096 32.538,30.045 14.96,30.045

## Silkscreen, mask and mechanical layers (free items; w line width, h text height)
Top Overlay:
  text "+" at 0.426,35.286 h1.02 r270
  text "+" at 6.268,32.723 h1.02 r270
  text "-" at 7.243,30.765 h1.02 r90
  text "-" at 0.426,29.118 h1.02 r270
  text "GND" at 14.932,22.611 h1 r270
  text "DAT" at 14.932,19.971 h1 r270
  text "3V3" at 14.932,17.331 h1 r270
  text "+" at 30.226,6.398 h1.02
  text "-" at 31.457,6.327 h1.02
  text "RST" at 1.193,3.299 h1
  text "GND" at 3.733,3.299 h1
  text "TX0" at 6.273,3.299 h1
  text "RX0" at 8.813,3.299 h1
  text "5V" at 11.553,3.299 h1
  text "+" at 27.609,0.296 h1.02
  text "-" at 33.777,0.296 h1.02
Bottom Overlay:
  region: 1.628,22.856 1.628,12.856 11.628,12.856 11.628,22.856
  text "微信扫一扫" at 12.414,10.14 h2.6
  text "WM_ASR_V2.0" at 34.774,1.233 h1.5

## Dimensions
0.338,35.149 to 36.338,35.149 on Mechanical 15
1.338,36.149 to 1.338,0.149 on Mechanical 15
